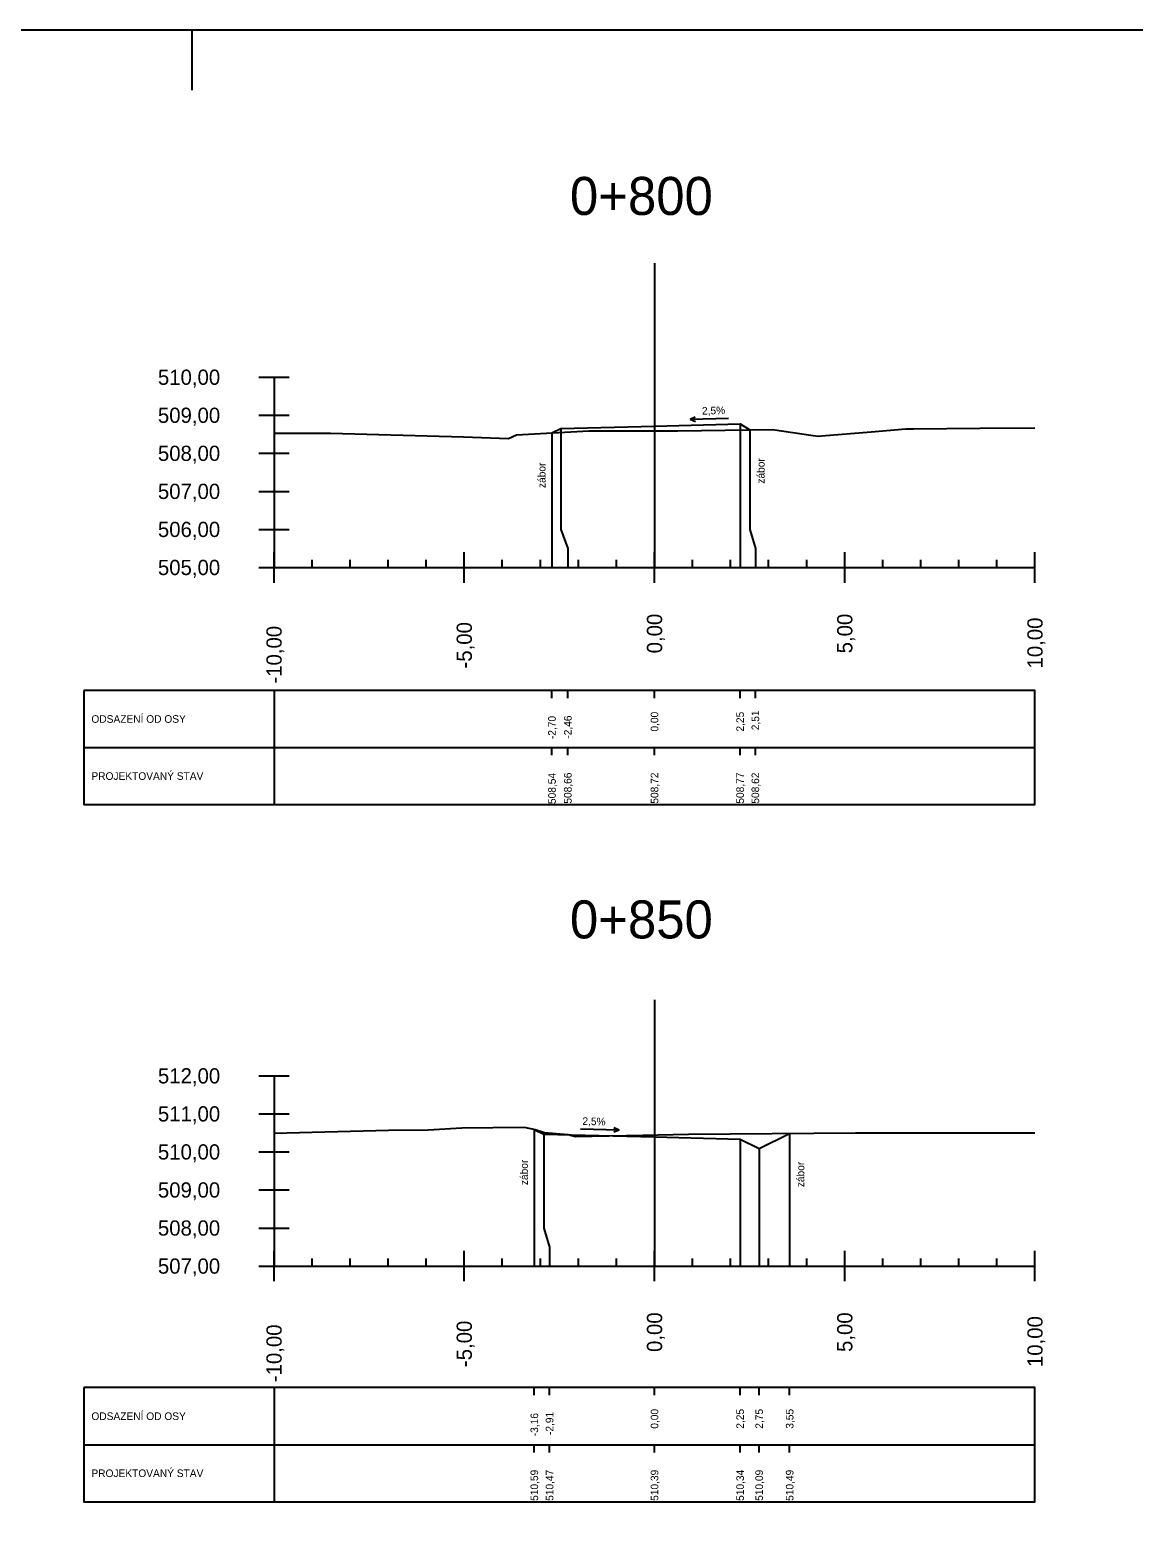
# Model space of a CAD drawing. Extents: x -631407 to -631215, y -1089700 to -1088598.
# Drawn here: x -631345.64 to -631316.63, y -1089150.59 to -1089110.96 of the extents above; entities that cross this region are included whole.
import ezdxf

# ---------------------------------------------------------------- set-up
doc = ezdxf.new("R2010")
doc.units = 0
for name, color, linetype in [('08_LEGENDA_HV', 7, 'Continuous'), ('59', 7, 'Continuous'), ('DTM-Breaklines', 7, 'Continuous'), ('NIVELETA_VYSKY', 7, 'Continuous'), ('REZ_BODY', 7, 'Continuous'), ('REZ_ODSTUPY', 7, 'Continuous'), ('REZ_POPIS', 7, 'Continuous'), ('REZ_RAMY', 7, 'Continuous'), ('REZ_STANICENI', 7, 'Continuous'), ('REZ_SVISLE', 7, 'Continuous'), ('REZ_TENKA', 7, 'Continuous'), ('REZ_TLUSTA', 7, 'Continuous'), ('TABULKA_POPIS', 7, 'Continuous'), ('TEREN', 7, 'Continuous'), ('zábor', 7, 'Continuous')]:
    doc.layers.add(name, color=color, linetype=linetype)

msp = doc.modelspace()

# ---------------------------------------------------------------- linework, layer by layer
at = {"layer": '08_LEGENDA_HV'}
msp.add_lwpolyline([(-631215.384, -1089270.801), (-631215.384, -1089110.964), (-631407.014, -1089110.964), (-631407.014, -1089270.801)], close=True, dxfattribs=at)
at = {"layer": '59'}
for p, q in [((-631339.63, -1089120.086), (-631338.83, -1089120.086)), ((-631339.23, -1089120.086), (-631339.23, -1089125.086)), ((-631339.63, -1089121.086), (-631338.83, -1089121.086)), ((-631339.63, -1089122.086), (-631338.83, -1089122.086)), ((-631339.63, -1089123.086), (-631338.83, -1089123.086)), ((-631339.63, -1089124.086), (-631338.83, -1089124.086)), ((-631339.63, -1089125.086), (-631338.83, -1089125.086)), ((-631339.63, -1089138.448), (-631338.83, -1089138.448)), ((-631339.23, -1089138.448), (-631339.23, -1089143.448)), ((-631339.63, -1089139.448), (-631338.83, -1089139.448)), ((-631339.63, -1089140.448), (-631338.83, -1089140.448)), ((-631339.63, -1089141.448), (-631338.83, -1089141.448)), ((-631339.63, -1089142.448), (-631338.83, -1089142.448)), ((-631339.63, -1089143.448), (-631338.83, -1089143.448))]:
    msp.add_line(p, q, dxfattribs=at)
at = {"layer": 'DTM-Breaklines'}
msp.add_line((-631341.384, -1089112.544), (-631341.384, -1089110.964), dxfattribs=at)
at = {"layer": 'REZ_RAMY'}
for p, q in [((-631344.23, -1089128.319), (-631344.23, -1089131.319)), ((-631339.23, -1089128.319), (-631339.23, -1089131.319)), ((-631331.925, -1089128.519), (-631331.925, -1089128.319)), ((-631331.509, -1089128.519), (-631331.509, -1089128.319)), ((-631329.23, -1089128.519), (-631329.23, -1089128.319)), ((-631326.98, -1089128.519), (-631326.98, -1089128.319)), ((-631326.58, -1089128.519), (-631326.58, -1089128.319)), ((-631344.23, -1089129.819), (-631319.23, -1089129.819)), ((-631331.925, -1089130.019), (-631331.925, -1089129.819)), ((-631331.509, -1089130.019), (-631331.509, -1089129.819)), ((-631329.23, -1089130.019), (-631329.23, -1089129.819)), ((-631326.98, -1089130.019), (-631326.98, -1089129.819)), ((-631326.58, -1089130.019), (-631326.58, -1089129.819)), ((-631344.23, -1089146.644), (-631344.23, -1089149.644)), ((-631339.23, -1089146.644), (-631339.23, -1089149.644)), ((-631332.389, -1089146.844), (-631332.389, -1089146.644)), ((-631331.989, -1089146.844), (-631331.989, -1089146.644)), ((-631329.23, -1089146.844), (-631329.23, -1089146.644)), ((-631326.98, -1089146.844), (-631326.98, -1089146.644)), ((-631326.48, -1089146.844), (-631326.48, -1089146.644)), ((-631325.678, -1089146.844), (-631325.678, -1089146.644)), ((-631344.23, -1089148.144), (-631319.23, -1089148.144)), ((-631332.389, -1089148.344), (-631332.389, -1089148.144)), ((-631331.989, -1089148.344), (-631331.989, -1089148.144)), ((-631329.23, -1089148.344), (-631329.23, -1089148.144)), ((-631326.98, -1089148.344), (-631326.98, -1089148.144)), ((-631326.48, -1089148.344), (-631326.48, -1089148.144)), ((-631325.678, -1089148.344), (-631325.678, -1089148.144))]:
    msp.add_line(p, q, dxfattribs=at)
for points in [[(-631344.23, -1089128.319), (-631344.23, -1089131.319), (-631319.23, -1089131.319), (-631319.23, -1089128.319)], [(-631344.23, -1089146.644), (-631344.23, -1089149.644), (-631319.23, -1089149.644), (-631319.23, -1089146.644)]]:
    msp.add_lwpolyline(points, close=True, dxfattribs=at)
at = {"layer": 'REZ_SVISLE'}
for points in [[(-631331.69, -1089121.431), (-631331.69, -1089124.086), (-631331.509, -1089124.586), (-631331.509, -1089125.086)], [(-631329.23, -1089121.37), (-631329.23, -1089124.086), (-631329.23, -1089124.586), (-631329.23, -1089125.086)], [(-631326.98, -1089121.313), (-631326.98, -1089124.086), (-631326.98, -1089124.586), (-631326.98, -1089125.086)], [(-631326.721, -1089121.468), (-631326.721, -1089124.086), (-631326.58, -1089124.586), (-631326.58, -1089125.086)], [(-631331.925, -1089121.549), (-631331.925, -1089124.086), (-631331.925, -1089124.586), (-631331.925, -1089125.086)], [(-631332.389, -1089139.857), (-631332.389, -1089142.448), (-631332.389, -1089142.948), (-631332.389, -1089143.448)], [(-631332.139, -1089139.982), (-631332.139, -1089142.448), (-631331.989, -1089142.948), (-631331.989, -1089143.448)], [(-631329.23, -1089140.055), (-631329.23, -1089142.448), (-631329.23, -1089142.948), (-631329.23, -1089143.448)], [(-631326.98, -1089140.111), (-631326.98, -1089142.448), (-631326.98, -1089142.948), (-631326.98, -1089143.448)], [(-631325.678, -1089139.96), (-631325.678, -1089142.448), (-631325.678, -1089142.948), (-631325.678, -1089143.448)], [(-631326.48, -1089140.361), (-631326.48, -1089142.448), (-631326.48, -1089142.948), (-631326.48, -1089143.448)]]:
    msp.add_lwpolyline(points, dxfattribs=at)
at = {"layer": 'REZ_TENKA'}
for p, q in [((-631338.23, -1089125.086), (-631338.23, -1089124.886)), ((-631337.23, -1089125.086), (-631337.23, -1089124.886)), ((-631336.23, -1089125.086), (-631336.23, -1089124.886)), ((-631335.23, -1089125.086), (-631335.23, -1089124.886)), ((-631333.23, -1089125.086), (-631333.23, -1089124.886)), ((-631332.23, -1089125.086), (-631332.23, -1089124.886)), ((-631331.23, -1089125.086), (-631331.23, -1089124.886)), ((-631330.23, -1089125.086), (-631330.23, -1089124.886)), ((-631328.23, -1089125.086), (-631328.23, -1089124.886)), ((-631327.23, -1089125.086), (-631327.23, -1089124.886)), ((-631326.23, -1089125.086), (-631326.23, -1089124.886)), ((-631325.23, -1089125.086), (-631325.23, -1089124.886)), ((-631323.23, -1089125.086), (-631323.23, -1089124.886)), ((-631322.23, -1089125.086), (-631322.23, -1089124.886)), ((-631321.23, -1089125.086), (-631321.23, -1089124.886)), ((-631320.23, -1089125.086), (-631320.23, -1089124.886)), ((-631338.23, -1089143.448), (-631338.23, -1089143.248)), ((-631337.23, -1089143.448), (-631337.23, -1089143.248)), ((-631336.23, -1089143.448), (-631336.23, -1089143.248)), ((-631335.23, -1089143.448), (-631335.23, -1089143.248)), ((-631333.23, -1089143.448), (-631333.23, -1089143.248)), ((-631332.23, -1089143.448), (-631332.23, -1089143.248)), ((-631331.23, -1089143.448), (-631331.23, -1089143.248)), ((-631330.23, -1089143.448), (-631330.23, -1089143.248)), ((-631328.23, -1089143.448), (-631328.23, -1089143.248)), ((-631327.23, -1089143.448), (-631327.23, -1089143.248)), ((-631326.23, -1089143.448), (-631326.23, -1089143.248)), ((-631325.23, -1089143.448), (-631325.23, -1089143.248)), ((-631323.23, -1089143.448), (-631323.23, -1089143.248)), ((-631322.23, -1089143.448), (-631322.23, -1089143.248)), ((-631321.23, -1089143.448), (-631321.23, -1089143.248)), ((-631320.23, -1089143.448), (-631320.23, -1089143.248))]:
    msp.add_line(p, q, dxfattribs=at)
at = {"layer": 'REZ_TLUSTA'}
for p, q in [((-631329.23, -1089117.086), (-631329.23, -1089125.086)), ((-631339.23, -1089125.486), (-631339.23, -1089124.686)), ((-631334.23, -1089125.486), (-631334.23, -1089124.686)), ((-631329.23, -1089125.486), (-631329.23, -1089124.686)), ((-631324.23, -1089125.486), (-631324.23, -1089124.686)), ((-631319.23, -1089125.486), (-631319.23, -1089124.686)), ((-631339.23, -1089125.086), (-631319.23, -1089125.086)), ((-631329.23, -1089136.448), (-631329.23, -1089143.448)), ((-631339.23, -1089143.848), (-631339.23, -1089143.048)), ((-631334.23, -1089143.848), (-631334.23, -1089143.048)), ((-631329.23, -1089143.848), (-631329.23, -1089143.048)), ((-631324.23, -1089143.848), (-631324.23, -1089143.048)), ((-631319.23, -1089143.848), (-631319.23, -1089143.048)), ((-631339.23, -1089143.448), (-631319.23, -1089143.448))]:
    msp.add_line(p, q, dxfattribs=at)
at = {"layer": 'TEREN'}
for points in [[(-631339.23, -1089121.56), (-631337.746, -1089121.558), (-631334.252, -1089121.653), (-631333.07, -1089121.698), (-631332.854, -1089121.603), (-631330.952, -1089121.492), (-631328.616, -1089121.499), (-631326.126, -1089121.459), (-631325.057, -1089121.619), (-631324.933, -1089121.635), (-631324.843, -1089121.625), (-631323.54, -1089121.52), (-631322.626, -1089121.44), (-631322.426, -1089121.44), (-631320.677, -1089121.427), (-631319.23, -1089121.419)], [(-631331.925, -1089121.549), (-631331.69, -1089121.431), (-631329.23, -1089121.37), (-631326.98, -1089121.313), (-631326.721, -1089121.468)], [(-631339.23, -1089139.952), (-631336.22, -1089139.872), (-631335.18, -1089139.866), (-631334.291, -1089139.818), (-631332.658, -1089139.801), (-631332.369, -1089139.862), (-631332.124, -1089139.941), (-631331.501, -1089139.989), (-631331.307, -1089140.04), (-631329.537, -1089140.004), (-631328.333, -1089139.98), (-631323.944, -1089139.947), (-631319.23, -1089139.949)], [(-631332.389, -1089139.857), (-631332.139, -1089139.982), (-631329.23, -1089140.055), (-631326.98, -1089140.111), (-631326.48, -1089140.361), (-631325.678, -1089139.96)]]:
    msp.add_lwpolyline(points, dxfattribs=at)
at = {"layer": 'zábor'}
for p, q in [((-631328.297, -1089121.19), (-631328.16, -1089121.125)), ((-631328.297, -1089121.19), (-631327.289, -1089121.165)), ((-631328.297, -1089121.19), (-631328.157, -1089121.248)), ((-631330.163, -1089139.875), (-631331.171, -1089139.85)), ((-631330.163, -1089139.875), (-631330.302, -1089139.933)), ((-631330.163, -1089139.875), (-631330.299, -1089139.811))]:
    msp.add_line(p, q, dxfattribs=at)

# ---------------------------------------------------------------- texts
at = {"layer": 'NIVELETA_VYSKY'}
for s, p in [('508,54', (-631331.825, -1089131.305)), ('508,66', (-631331.409, -1089131.295)), ('508,72', (-631329.13, -1089131.295)), ('508,77', (-631326.88, -1089131.295)), ('508,62', (-631326.48, -1089131.295)), ('510,59', (-631332.289, -1089149.62)), ('510,47', (-631331.889, -1089149.62)), ('510,39', (-631329.13, -1089149.62)), ('510,34', (-631326.88, -1089149.62)), ('510,09', (-631326.38, -1089149.62)), ('510,49', (-631325.578, -1089149.62))]:
    msp.add_text(s, height=0.2, rotation=90, dxfattribs=at).set_placement(p)
at = {"layer": 'REZ_BODY'}
for s, p in [('-2,70', (-631331.825, -1089129.597)), ('-2,46', (-631331.409, -1089129.587)), ('0,00', (-631329.13, -1089129.399)), ('2,25', (-631326.88, -1089129.399)), ('2,51', (-631326.48, -1089129.365)), ('0,00', (-631329.13, -1089147.723)), ('2,25', (-631326.88, -1089147.723)), ('2,75', (-631326.38, -1089147.723)), ('3,55', (-631325.578, -1089147.723)), ('-3,16', (-631332.289, -1089147.921)), ('-2,91', (-631331.889, -1089147.888))]:
    msp.add_text(s, height=0.2, rotation=90, dxfattribs=at).set_placement(p)
at = {"layer": 'REZ_ODSTUPY'}
for s, p in [('-10,00', (-631339.03, -1089128.138)), ('-5,00', (-631334.03, -1089127.741)), ('0,00', (-631329.03, -1089127.344)), ('5,00', (-631324.03, -1089127.344)), ('10,00', (-631319.03, -1089127.741)), ('0,00', (-631329.03, -1089145.706)), ('5,00', (-631324.03, -1089145.706)), ('10,00', (-631319.03, -1089146.103)), ('-10,00', (-631339.03, -1089146.5)), ('-5,00', (-631334.03, -1089146.103))]:
    msp.add_text(s, height=0.4, rotation=90, dxfattribs=at).set_placement(p)
at = {"layer": 'REZ_POPIS'}
for s, p in [('510,00', (-631342.282, -1089120.286)), ('509,00', (-631342.282, -1089121.286)), ('508,00', (-631342.282, -1089122.286)), ('507,00', (-631342.282, -1089123.286)), ('506,00', (-631342.282, -1089124.286)), ('505,00', (-631342.282, -1089125.286)), ('512,00', (-631342.282, -1089138.648)), ('511,00', (-631342.282, -1089139.648)), ('510,00', (-631342.282, -1089140.648)), ('509,00', (-631342.282, -1089141.648)), ('508,00', (-631342.282, -1089142.648)), ('507,00', (-631342.282, -1089143.648))]:
    msp.add_text(s, height=0.4, dxfattribs=at).set_placement(p)
at = {"layer": 'REZ_STANICENI'}
for s, p in [('0+800', (-631331.453, -1089115.821)), ('0+850', (-631331.453, -1089134.837))]:
    msp.add_text(s, height=1, dxfattribs=at).set_placement(p)
at = {"layer": 'TABULKA_POPIS'}
for s, p in [('ODSAZENÍ OD OSY', (-631344.03, -1089129.169)), ('PROJEKTOVANÝ STAV', (-631344.03, -1089130.669)), ('ODSAZENÍ OD OSY', (-631344.03, -1089147.494)), ('PROJEKTOVANÝ STAV', (-631344.03, -1089148.994))]:
    msp.add_text(s, height=0.2, dxfattribs=at).set_placement(p)
at = {"layer": 'zábor'}
for s, rotation, p in [('2,5%', 1.4321, (-631327.98, -1089121.069)), ('zábor', 90, (-631326.338, -1089122.883)), ('zábor', 90, (-631332.095, -1089122.999)), ('2,5%', 358.5679, (-631331.127, -1089139.738)), ('zábor', 90, (-631332.559, -1089141.321)), ('zábor', 90, (-631325.295, -1089141.375))]:
    msp.add_text(s, height=0.2, rotation=rotation, dxfattribs=at).set_placement(p)

doc.saveas('drawing.dxf')
